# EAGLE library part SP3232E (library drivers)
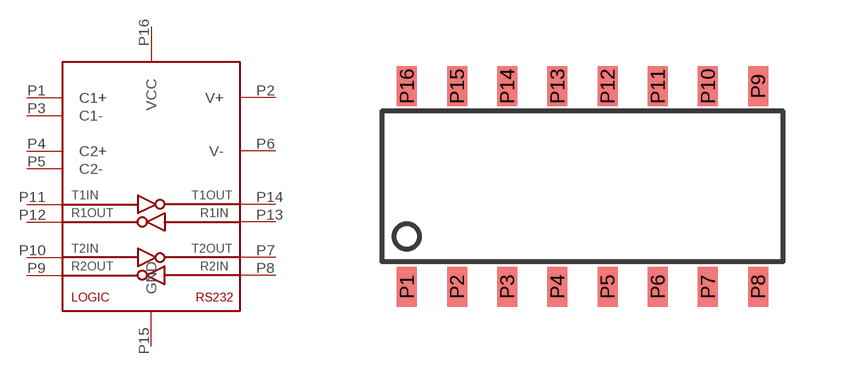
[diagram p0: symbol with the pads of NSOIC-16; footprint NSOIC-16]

Designator prefix -

## SP3232E  [NSOIC-16]
P1  C1+  pwr
P2  V+  pwr
P3  C1-  pwr
P4  C2+  pwr
P5  C2-  pwr
P6  V-  pwr
P7  T2OUT  out
P8  R2IN  in
P9  R2OUT  out
P10  T2IN  in
P11  T1IN  in
P12  R1OUT  out
P13  R1IN  in
P14  T1OUT  out
P15  GND  pwr
P16  VCC  pwr

## Footprint NSOIC-16 (pad centres in mm)
smd 0.508 x 1.016: P1 -4.445,-2.54; P2 -3.175,-2.54; P3 -1.905,-2.54; P4 -0.635,-2.54; P5 0.635,-2.54; P6 1.905,-2.54; P7 3.175,-2.54; P8 4.445,-2.54; P9 4.445,2.54; P10 3.175,2.54; P11 1.905,2.54; P12 0.635,2.54; P13 -0.635,2.54; P14 -1.905,2.54; P15 -3.175,2.54; P16 -4.445,2.54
